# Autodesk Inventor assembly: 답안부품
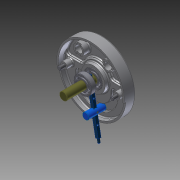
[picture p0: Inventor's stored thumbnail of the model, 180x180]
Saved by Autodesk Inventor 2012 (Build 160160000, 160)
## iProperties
Created: 2015-04
Part Number: 답안부품
Document SubType Name: Assembly
Designer: Owner
Author: Owner
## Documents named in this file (9)
- C:\Documents and Settings\Owner\바탕 화면\450405V1001\답안부품.iam
- C:\Documents and Settings\Owner\바탕 화면\450405V1001\본체.ipt
- C:\Documents and Settings\Owner\바탕 화면\450405V1001\베어링62_22.ipt
- C:\Documents and Settings\Owner\바탕 화면\450405V1001\덮개.ipt
- C:\Documents and Settings\Owner\바탕 화면\450405V1001\축.ipt
- C:\Documents and Settings\Owner\바탕 화면\450405V1001\평행핀.ipt
- C:\Documents and Settings\Owner\바탕 화면\450405V1001\슬라이더.ipt
- C:\Documents and Settings\Owner\바탕 화면\450405V1001\슬라이더2.ipt
- C:\Documents and Settings\Owner\바탕 화면\450405V1001\M 10 x 35.ipt
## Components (2 placed, 1 different names)
1. M 10 x 35:1
2. M 10 x 35:2
